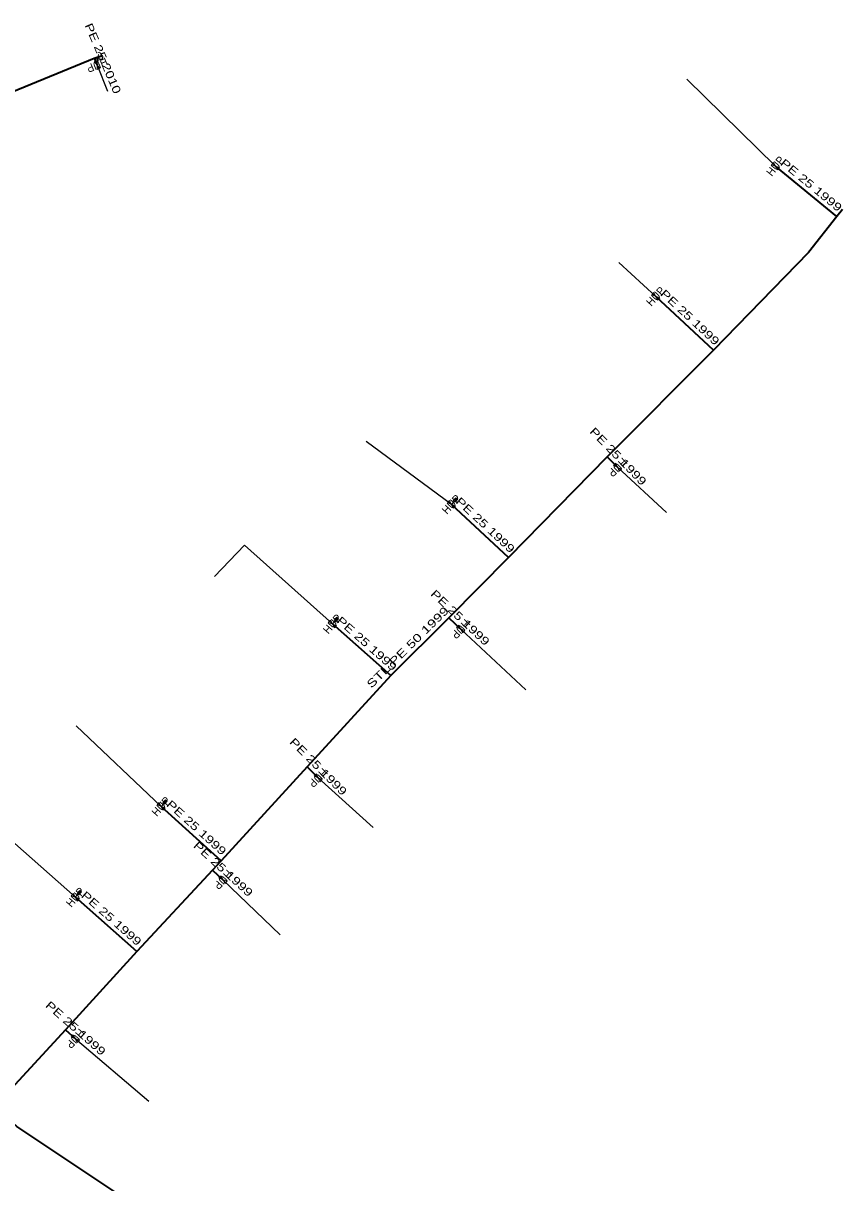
# Model space of a CAD drawing. Extents: x -737484 to -734496, y -1033882 to -1030666.
# Drawn here: x -736358.7 to -736256.4, y -1032475.7 to -1032330.8 of the extents above; entities that cross this region are included whole.
import ezdxf
from ezdxf.enums import TextEntityAlignment as Align

# ---------------------------------------------------------------- set-up
doc = ezdxf.new("R2010")
doc.units = 0
doc.header["$LTSCALE"] = 0.4
for name, color, linetype, lineweight in [('1', 7, 'Continuous', 13), ('22', 7, 'Continuous', 25), ('5', 7, 'Continuous', 35), ('7', 7, 'Continuous', 35)]:
    doc.layers.add(name, color=color, linetype=linetype, lineweight=lineweight)
doc.layers.add('2', color=7, linetype='Continuous')

msp = doc.modelspace()

# ---------------------------------------------------------------- linework, layer by layer
at = {"layer": '1'}
for p, q in [((-736349.469, -1032336.01), (-736349.469, -1032335.51)), ((-736349.394, -1032335.435), (-736349.394, -1032335.085)), ((-736305.199, -1032390.909), (-736304.858, -1032390.543)), ((-736304.751, -1032390.539), (-736304.513, -1032390.283)), ((-736320.07, -1032405.849), (-736319.741, -1032405.471)), ((-736319.636, -1032405.464), (-736319.406, -1032405.2)), ((-736341.479, -1032428.66), (-736341.144, -1032428.288)), ((-736341.038, -1032428.282), (-736340.804, -1032428.022)), ((-736352.19, -1032440), (-736351.861, -1032439.622)), ((-736351.756, -1032439.615), (-736351.526, -1032439.351))]:
    msp.add_line(p, q, dxfattribs=at)
msp.add_lwpolyline([(-736349.375, -1032334.504), (-736349.148, -1032334.399), (-736348.729, -1032335.308), (-736348.956, -1032335.412)], dxfattribs=at)
for points in [[(-736349.089, -1032336.392), (-736349.457, -1032336.548), (-736349.48, -1032335.471), (-736349.848, -1032335.627)], [(-736349.469, -1032335.01), (-736349.619, -1032335.01), (-736349.619, -1032335.51), (-736349.469, -1032335.51)], [(-736349.469, -1032335.01), (-736349.319, -1032335.01), (-736349.319, -1032335.51), (-736349.469, -1032335.51)], [(-736349.432, -1032335.048), (-736349.357, -1032335.048), (-736349.357, -1032335.473), (-736349.432, -1032335.473)], [(-736265.214, -1032348.48), (-736264.962, -1032348.169), (-736264.437, -1032349.11), (-736264.185, -1032348.799)], [(-736280.171, -1032364.724), (-736279.898, -1032364.431), (-736279.439, -1032365.406), (-736279.166, -1032365.113)], [(-736283.938, -1032386.499), (-736284.226, -1032386.777), (-736284.633, -1032385.78), (-736284.921, -1032386.058)], [(-736305.7, -1032390.715), (-736305.427, -1032390.422), (-736304.968, -1032391.397), (-736304.695, -1032391.104)], [(-736304.517, -1032390.177), (-736304.626, -1032390.075), (-736304.967, -1032390.441), (-736304.858, -1032390.543)], [(-736304.517, -1032390.177), (-736304.407, -1032390.279), (-736304.748, -1032390.645), (-736304.858, -1032390.543)], [(-736304.515, -1032390.23), (-736304.461, -1032390.281), (-736304.75, -1032390.592), (-736304.805, -1032390.541)], [(-736320.576, -1032405.671), (-736320.314, -1032405.37), (-736319.821, -1032406.327), (-736319.559, -1032406.026)], [(-736319.413, -1032405.094), (-736319.527, -1032404.995), (-736319.855, -1032405.373), (-736319.741, -1032405.471)], [(-736319.413, -1032405.094), (-736319.3, -1032405.192), (-736319.628, -1032405.57), (-736319.741, -1032405.471)], [(-736319.41, -1032405.147), (-736319.354, -1032405.196), (-736319.633, -1032405.517), (-736319.689, -1032405.467)], [(-736303.534, -1032406.682), (-736303.807, -1032406.975), (-736304.266, -1032406), (-736304.539, -1032406.293)], [(-736321.355, -1032425.292), (-736321.637, -1032425.574), (-736322.062, -1032424.585), (-736322.344, -1032424.867)], [(-736341.982, -1032428.472), (-736341.714, -1032428.174), (-736341.239, -1032429.141), (-736340.971, -1032428.843)], [(-736340.809, -1032427.916), (-736340.921, -1032427.816), (-736341.255, -1032428.188), (-736341.144, -1032428.288)], [(-736340.809, -1032427.916), (-736340.698, -1032428.017), (-736341.032, -1032428.388), (-736341.144, -1032428.288)], [(-736340.807, -1032427.969), (-736340.752, -1032428.02), (-736341.036, -1032428.335), (-736341.092, -1032428.285)], [(-736333.232, -1032437.994), (-736333.5, -1032438.292), (-736333.975, -1032437.325), (-736334.243, -1032437.623)], [(-736352.696, -1032439.822), (-736352.434, -1032439.521), (-736351.941, -1032440.478), (-736351.679, -1032440.177)], [(-736351.533, -1032439.245), (-736351.647, -1032439.146), (-736351.975, -1032439.524), (-736351.861, -1032439.622)], [(-736351.533, -1032439.245), (-736351.42, -1032439.343), (-736351.748, -1032439.721), (-736351.861, -1032439.622)], [(-736351.53, -1032439.298), (-736351.474, -1032439.347), (-736351.753, -1032439.668), (-736351.809, -1032439.618)], [(-736351.689, -1032457.846), (-736351.951, -1032458.147), (-736352.444, -1032457.19), (-736352.706, -1032457.491)]]:
    msp.add_lwpolyline(points, close=True, dxfattribs=at)
at = {"layer": '22'}
for p, q in [((-736349.469, -1032336.01), (-736348.163, -1032339.29)), ((-736264.7, -1032348.64), (-736275.789, -1032337.788)), ((-736279.669, -1032364.919), (-736284.27, -1032360.677)), ((-736305.199, -1032390.91), (-736315.85, -1032383.069)), ((-736284.43, -1032386.28), (-736278.328, -1032391.945)), ((-736304.038, -1032406.489), (-736295.908, -1032414.092)), ((-736341.479, -1032428.659), (-736352.069, -1032418.57)), ((-736321.85, -1032425.08), (-736314.954, -1032431.274)), ((-736352.189, -1032440), (-736362.976, -1032430.459)), ((-736333.739, -1032437.809), (-736326.593, -1032444.709)), ((-736352.199, -1032457.669), (-736342.994, -1032465.473))]:
    msp.add_line(p, q, dxfattribs=at)
msp.add_lwpolyline([(-736320.069, -1032405.849), (-736331.07, -1032396.016), (-736334.814, -1032399.924)], dxfattribs=at)
at = {"layer": '5'}
for points in [[(-736403.749, -1032357.15), (-736400.684, -1032355.759), (-736395.181, -1032353.489), (-736384.49, -1032349.247), (-736374.582, -1032345.179), (-736369.657, -1032343.269), (-736349.842, -1032335.135), (-736348.939, -1032334.854)], [(-736256.34, -1032354.06), (-736257.03, -1032354.95), (-736260.59, -1032359.44), (-736272.46, -1032371.63), (-736285.72, -1032384.95), (-736298.08, -1032397.54), (-736305.52, -1032405.1), (-736312.78, -1032412.28), (-736323.22, -1032423.701), (-736333.96, -1032435.45), (-736335.03, -1032436.63), (-736344.49, -1032446.8), (-736353.42, -1032456.59), (-736361.22, -1032465.02), (-736362.27, -1032466.2)], [(-736281.54, -1032520.32), (-736305.46, -1032504.54), (-736314.51, -1032498.76), (-736326.73, -1032490.8), (-736344.11, -1032478.91), (-736359.52, -1032468.66), (-736362.27, -1032466.2)]]:
    msp.add_lwpolyline(points, dxfattribs=at)
at = {"layer": '7'}
for p, q in [((-736349.842, -1032335.135), (-736349.469, -1032336.01)), ((-736257.03, -1032354.95), (-736264.7, -1032348.64)), ((-736272.46, -1032371.63), (-736279.669, -1032364.919)), ((-736285.72, -1032384.95), (-736284.43, -1032386.279)), ((-736298.08, -1032397.54), (-736305.198, -1032390.91)), ((-736305.52, -1032405.1), (-736304.037, -1032406.488)), ((-736312.78, -1032412.28), (-736320.068, -1032405.849)), ((-736323.22, -1032423.701), (-736321.85, -1032425.08)), ((-736333.96, -1032435.45), (-736341.477, -1032428.658)), ((-736335.03, -1032436.63), (-736333.738, -1032437.809)), ((-736344.49, -1032446.8), (-736352.188, -1032440)), ((-736353.42, -1032456.59), (-736352.198, -1032457.669))]:
    msp.add_line(p, q, dxfattribs=at)

# ---------------------------------------------------------------- texts
at = {"layer": '2', "width": 0.95}
for rotation, p in [(203, (-736349.6641, -1032335.5493)), (51, (-736264.3112, -1032348.9542)), (47, (-736279.303, -1032365.2595)), (224, (-736284.7762, -1032385.9184)), (47, (-736304.832, -1032391.2505)), (49, (-736319.6904, -1032406.1765)), (227, (-736304.402, -1032406.1465)), (225, (-736322.2029, -1032424.7259)), (48, (-736341.1053, -1032428.9921)), (228, (-736334.1087, -1032437.4739)), (49, (-736351.8104, -1032440.3275)), (229, (-736352.5746, -1032457.3405))]:
    msp.add_text('HUP', height=1, rotation=rotation, dxfattribs=at).set_placement(p, align=Align.CENTER)
at = {"layer": '5', "width": 1.4}
msp.add_text('STL PE 50 1999', height=1, rotation=44.683, dxfattribs=at).set_placement((-736310.3091, -1032409.1332), align=Align.CENTER)
at = {"layer": '7', "width": 1.35}
for s, rotation, p in [('PE 25 2010', 293.088, (-736349.195, -1032335.3759)), ('PE 25 1999', 320.556, (-736260.5472, -1032351.4087)), ('PE 25 1999', 317.049, (-736275.7232, -1032367.9081)), ('PE 25 1999', 314.147, (-736284.7158, -1032385.2653)), ('PE 25 1999', 317.033, (-736301.2978, -1032393.8585)), ('PE 25 1999', 316.895, (-736304.4362, -1032405.4284)), ('PE 25 1999', 318.575, (-736316.0928, -1032408.6891)), ('PE 25 1999', 314.812, (-736322.1796, -1032424.0376)), ('PE 25 1999', 317.901, (-736337.3832, -1032431.6824)), ('PE 25 1999', 317.618, (-736334.0465, -1032436.8495)), ('PE 25 1999', 318.544, (-736348.0075, -1032443.0249)), ('PE 25 1999', 318.556, (-736352.4774, -1032456.7546))]:
    msp.add_text(s, height=1, rotation=rotation, dxfattribs=at).set_placement(p, align=Align.CENTER)

doc.saveas('drawing.dxf')
